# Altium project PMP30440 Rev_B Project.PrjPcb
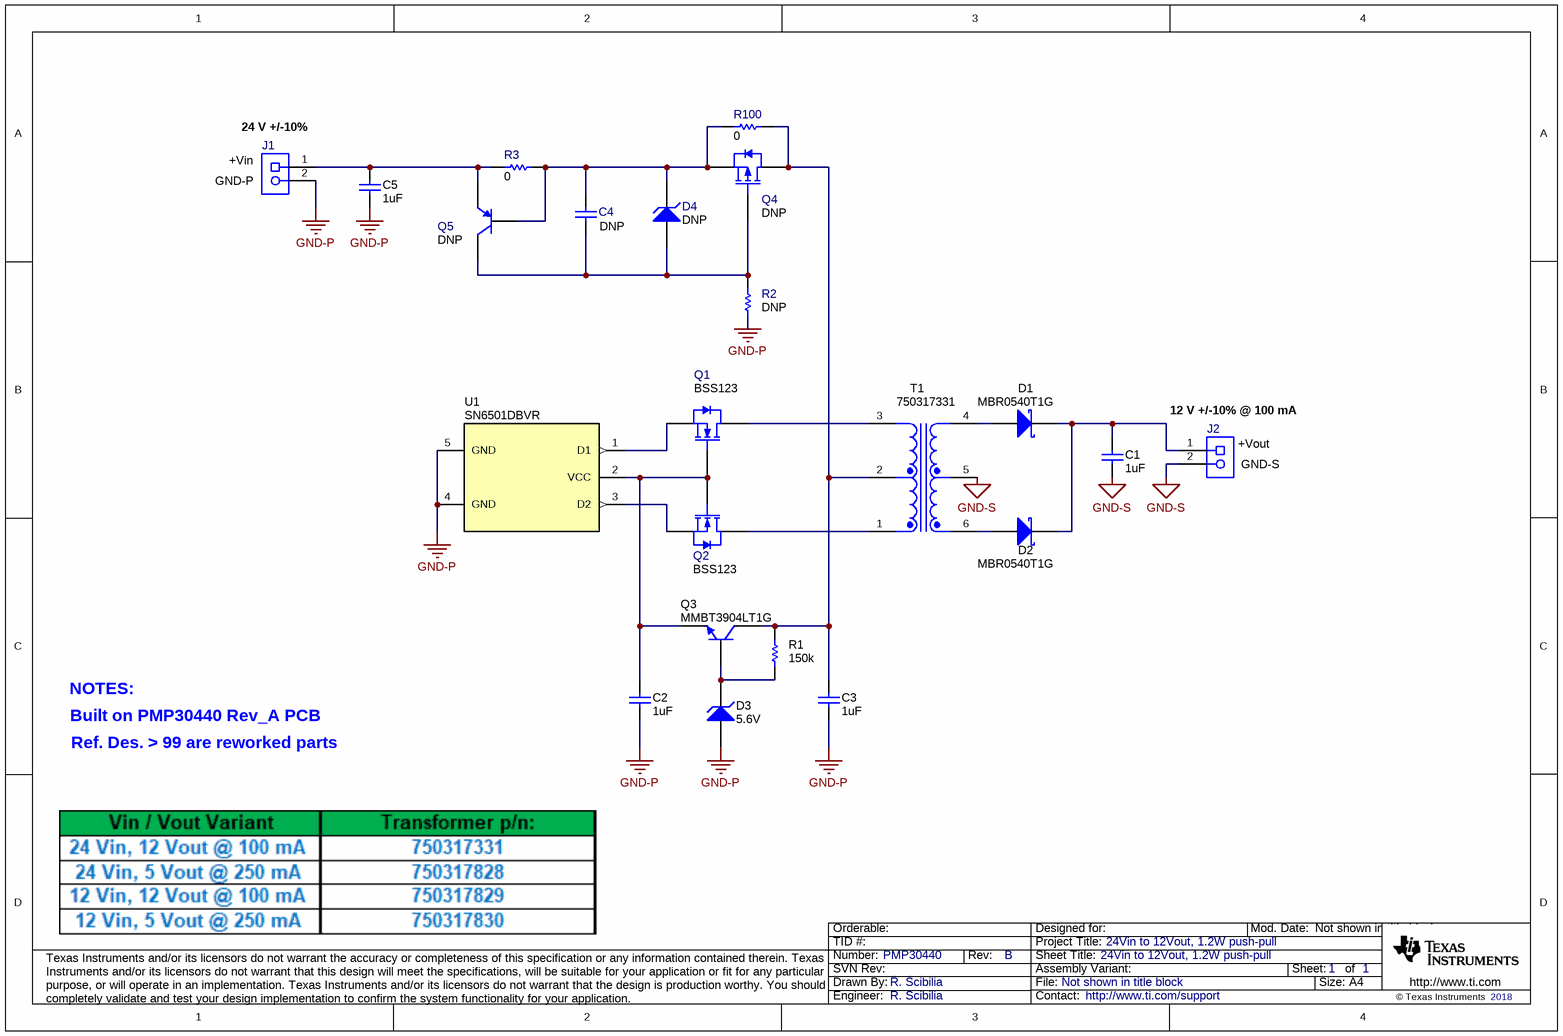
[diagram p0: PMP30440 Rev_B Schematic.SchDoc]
TechSupport: http://www.ti.com/support; SCH_Rev: B; PRJ_Title: 24Vin to 12Vout, 1.2W push-pull; PRJ_Number: PMP30440; PRJ_Engineer: R. Scibilia; PCB_Rev: A; PCB_Layout: R. Scibilia; CopyrightYear: 2018
1 sheet, 22 parts. Net scope: global (net labels, ports and power ports of the same name join across sheets).
Board file: PMP30440 Rev_A PCB.PcbDoc

## Sheet PMP30440 Rev_B Schematic.SchDoc: 24Vin to 12Vout, 1.2W push-pull
size A4; Date: Not shown in title block; ApprovedBy: Not shown in title block; CheckedBy: Not shown in title block; Author: Not shown in title block; CompanyName: Not shown in title block; DrawnBy: R. Scibilia; Engineer: Not shown in title block; Organization: Not shown in title block; Address1: Not shown in title block; Address2: Not shown in title block; Address3: Not shown in title block; Address4: Not shown in title block; DocumentNumber: 1; Revision: Use project parameter SCH_Rev; SheetNumber: 1; SheetTotal: 1; PageSetup: Record=PageOptions¦CenterHorizontal=True¦CenterVertical=True¦PrintScale=1.00¦XCorrection=1.00¦YCorrection=1.00¦PrintKind=0¦BorderSize=5000000¦LeftOffset=0¦BottomOffset=0¦Orientation=2¦PaperLength=1000¦PaperWidth=1000¦Scale=100¦PaperSource=15¦PrintQuality=600¦MediaType=1¦DitherType=10¦PaperKind=Letter¦PrintScaleMode=1

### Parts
C1  value 1uF  [0603]  (hidden comment: C1608X5R1H105K080AB)
C2  value 1uF  [0603]  (hidden comment: C1608X5R1H105K080AB)
C3  value 1uF  [0603]  (hidden comment: C1608X5R1H105K080AB)
C4  DNP  [0603]
C5  value 1uF  [0603]  (hidden comment: C1608X5R1H105K080AB)
D1  MBR0540T1G  [SOD-123]
D2  MBR0540T1G  [SOD-123]
D3  value 5.6V  [SOD-523]  (hidden comment: BZT52C5V6T-7)
D4  DNP  [SOD-523]
J1  39357-0002  [Molex_39357-0002]  (value not drawn)
J2  39357-0002  [Molex_39357-0002]  (value not drawn)
Q1  BSS123  [SOT-23]
Q2  BSS123  [SOT-23]
Q3  MMBT3904LT1G  [SOT-23]
Q4  DNP  [SOT-23]
Q5  DNP  [SOT-23]
R1  ValueDisplayed: 150k  [0603]  (hidden comment: RC0603FR-07150KL)
R2  DNP  [0603]
R3  ValueDisplayed: 0  [5106]  (hidden comment: 5106)
R100  ValueDisplayed: 0  [5106]  (hidden comment: 5106)
T1  750317331  [Wurth_760390012]
U1  SN6501DBVR  [DBV0005A_N]

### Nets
GND-P: C2.2 C3.2 C5.2 D3.2(A) J1.2 R2.1 U1.4(GND) U1.5(GND)
GND-S: C1.2 J2.2 T1.5
NetC1_1: C1.1 D1.1(K) D2.1(K) J2.1
NetC2_1: C2.1 Q1.1(G) Q2.1(G) Q3.2(E) U1.2(VCC)
NetC3_1: C3.1 Q3.3(C) Q4.3(D) R1.2 R100.2 T1.2
NetC4_1: C4.1 D4.1(K) Q4.2(S) Q5.1(B) R3.2 R100.1
NetC4_2: C4.2 D4.2(A) Q4.1(G) Q5.3(C) R2.2
NetC5_1: C5.1 J1.1 Q5.2(E) R3.1
NetD1_2: D1.2(A) T1.4
NetD2_2: D2.2(A) T1.6
NetD3_1: D3.1(K) Q3.1(B) R1.1
NetQ1_2: Q1.2(S) U1.1(D1)
NetQ1_3: Q1.3(D) T1.3
NetQ2_2: Q2.2(S) U1.3(D2)
NetQ2_3: Q2.3(D) T1.1

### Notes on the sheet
- (near J1) GND-P
- (near J1) +Vin
- (near J1) 24 V +/-10%
- (near J2) 12 V +/-10% @ 100 mA
- (near J2) +Vout
- (near J2) GND-S
- NOTES:
- Built on PMP30440 Rev_A PCB
- Ref. Des. > 99 are reworked parts

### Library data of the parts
C1-C3 C5 = C1608X5R1H105K080AB: CAP, CERM, 1 µF, 50 V,+/- 10%, X5R, 0603; Manufacturer: TDK; Polarized: N; CompType: Capacitor; ValueDisplayed: 1µF; U/M: EA; Cap_F: 0.000001; Tolerance_%: 10; ESR_ohm: 0.005522; Value1: 0.005522 ohm; VDC_V: 50; Value2: 50V; IRMS_A: 2.21617; TaMin_C: -55; TaMax_C: 85; SizeArea_mm2: 1.28; SizeAreaWB_mm2: 4.68; SizeX_mm: 1.6; SizeY_mm: 0.8; SizeZ_mm: 1; AEC Category: Q200; Green_Lifecycle: Active; Green_REACh: Passed
C4 = GRM188R61H102KA01D: Polarized: N; CompType: Capacitor; U/M: EA; Cap_F: 0.000000001; Tolerance_%: 10; VDC_V: 50; Value2: 50V; TempCo: X5R; TaMin_C: -55; TaMax_C: 85; SizeArea_mm2: 1.28; SizeAreaWB_mm2: 4.68; SizeX_mm: 1.6; SizeY_mm: 0.8; SizeZ_mm: 1; AEC Category: Q200; Green_Lifecycle: Active; Green_REACh: Passed
D1 D2 = MBR0540T1G: Diode, Schottky, 40 V, 0.5 A, SOD-123; Manufacturer: ON Semiconductor; U/M: EA; Vf_V: 0.51; Value: 40V; Value1: 0.5A; Value2: 0.51V; Io_A: 0.5; Vr_V: 40; TJmax_C: 150; RJC_CperW: 118; SizeAreaWB_mm2: 13.095; SizeArea_mm2: 6.545; SizeX_mm: 3.85; SizeY_mm: 1.7; SizeZ_mm: 1.35; AEC Category: Q101; Green_Lifecycle: Active; Green_REACh: Passed
D3 = BZT52C5V6T-7: Diode, Zener, 5.6 V, 300 mW, SOD-523; Manufacturer: Diodes Inc.; SymbolCreator: a0412235; U/M: EA; Power_W: 0.3; Vz_V: 5.6; Value1: 0.3W; RJA_CperW: 417; SizeAreaWB_mm2: 5.13; SizeArea_mm2: 1.53; SizeX_mm: 1.7; SizeY_mm: 0.9; SizeZ_mm: 0.65; AEC Category: Q101; Green_Lifecycle: Active; Green_REACh: Passed
D4 = BZT52C12T-7: SymbolCreator: a0412235; CompType: Zener; U/M: EA; Power_W: 0.3; Vz_V: 12; Value1: 0.3W; RJA_CperW: 417; SizeAreaWB_mm2: 5.13; SizeArea_mm2: 1.53; SizeX_mm: 1.7; SizeY_mm: 0.9; SizeZ_mm: 0.65; AEC Category: Q101
J1 J2 = 39357-0002: Terminal Block, 3.5 mm, 2x1, Tin, TH; Manufacturer: Molex; SymbolCreator: a0412235; Green_Lifecycle: Not Set; Green_REACh: Incomplete
Q1 Q2 = BSS123: MOSFET, N-CH, 100 V, 0.17 A, SOT-23; Manufacturer: Fairchild Semiconductor; Alternate Manufacturer: None; U/M: EA; ChType: N; Value: 100V; VdsMax_V: 100; Value1: 10 ohm; Rdson45_ohm: 10; Value2: 1.8 nC; QgTyp_nC: 1.8; Vgs_V: 20; IdsMax_A: 0.17; SizeAreaWB_mm2: 14; SizeArea_mm2: 7.5; SizeX_mm: 2.5; SizeY_mm: 3; SizeZ_mm: 1.1; AEC Category: Q101; Green_Lifecycle: Active; Green_REACh: Passed
Q3 = MMBT3904LT1G, ON Semiconductor: Transistor, NPN, 40 V, 0.2 A, SOT-23; CompType: BJT; PNP: 0; NPN: 1; Vceo_V: 40; Vcesat1_V: 0.3; Value: 40 V; IcRated_A: 0.2; Value1: 0.2 A; HfeMax: 300; TaMin_C: -55; TaMax_C: 150; SizeAreaWB_mm2: 14; SizeArea_mm2: 7.5; SizeX_mm: 2.5; SizeY_mm: 3; SizeZ_mm: 1.1; U/M: EA; AEC Category: Q101; Green_Lifecycle: Active; Green_REACh: Passed
Q4 = BSR316PH6327XTSA1: Alternate Manufacturer: None; CompType: MOSFET; U/M: EA; ChType: P; VdsMax_V: -60; Rdson45_ohm: 2.2; Value2: 1 nC; QgTyp_nC: 5.3; Vgs_V: -20; IdsMax_A: -0.36; SizeAreaWB_mm2: 14; SizeArea_mm2: 7.5; SizeX_mm: 2.5; SizeY_mm: 3; SizeZ_mm: 1.1; AEC Category: Q101; AEC Qualified: Y
Q5 = MMBT3906, Fairchild Semiconductor: CompType: BJT; PNP: 1; NPN: 0; Vceo_V: 40; Vcesat1_V: 0.25; IcRated_A: 0.2; Value1: 0.2 A; HfeMax: 300; TaMin_C: -55; TaMax_C: 150; SizeAreaWB_mm2: 14; SizeArea_mm2: 7.5; SizeX_mm: 2.5; SizeY_mm: 3; SizeZ_mm: 1.1; U/M: EA; AEC Category: Q101; Green_Lifecycle: Active; Green_REACh: Passed
R1 = RC0603FR-07150KL: RES, 150 k, 1%, 0.1 W, 0603; Manufacturer: Yageo America; CompType: Resistor; Value: 150k; Res_ohm: 150000; Tolerance_%: 1; Power_W: 0.1; Value2: 0.1W; VDC_V: 150; TempCo: 200 ppm/C; SizeArea_mm2: 1.28; SizeX_mm: 1.6; SizeY_mm: 0.8; EIA_Code: E96; U/M: EA; AEC Category: Q200; Green_Lifecycle: Active; Green_REACh: Passed
R2 = CRCW0603100KFKEA: CompType: Resistor; Res_ohm: 100000; Tolerance_%: 1; Value1: 1%; Power_W: 0.1; Value2: 0.1W; VDC_V: 75; TempCo: 100 ppm/C; SizeArea_mm2: 1.28; SizeX_mm: 1.6; SizeY_mm: 0.8; EIA_Code: E96; U/M: EA; AEC Category: Q200; Green_Lifecycle: Active; Green_REACh: Passed
R3 R100 = CMP-0020833-2: RES, 0, 1%, 0.5 W, 0805; Manufacturer: Keystone; Power_W: 500mW; TempCo: ppm/C; U/M: EA; Value: 0; SizeX_mm: 2; SizeY_mm: 1.25; SizeZ_mm: 0.84; Value2: 0.5W; SizeArea_mm2: 2.5; AEC Qualified: N; AEC Category: Q200
T1 = 760390012: Transformer, 1 mH, SMT; Manufacturer: Wurth Elektronik; SymbolCreator: Altium; ValueDisplayed: 1mH; DCR_ohm: 1.4; Lp: 475; Ind_H: 0.001; Ns1toNp: 1.94:1; Rsec1_ohm: 0.6; SizeAreaWB_mm2: 105.1965; SizeArea_mm2: 67.6365; SizeX_mm: 10.05; SizeY_mm: 6.73; SizeZ_mm: 4.19
U1 = SN6501DBVR: Low-Noise 350 mA, 410 kHz Transformer Driver, DBV0005A (SOT-23-5); Alternate PartNumber: SN6501DBVT; Manufacturer: Texas Instruments; SymbolCreator: a0411947; SizeArea_mm2: 8.12; SizeAreaWB_mm2: 14.82; SizeX_mm: 2.8; SizeY_mm: 2.9; SizeZ_mm: 1.45; CompType: IC; U/M: EA; Green_Lifecycle: Not Set; Green_REACh: Passed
